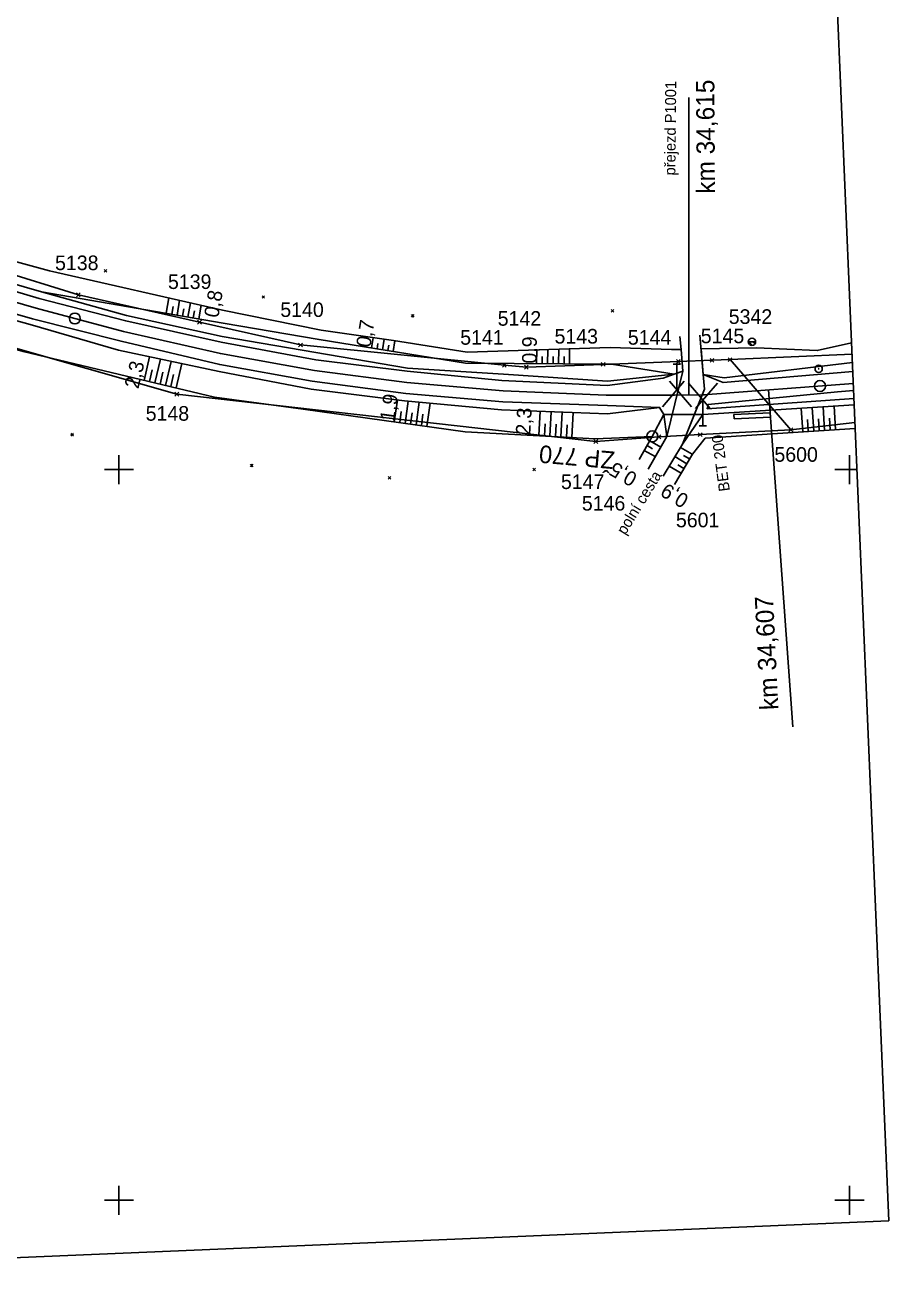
# Model space of a CAD drawing. Extents: x -806456 to -805395, y -1150847 to -1150506.
# Drawn here: x -805512.8 to -805394.6, y -1150811.7 to -1150639.2 of the extents above; entities that cross this region are included whole.
import ezdxf

# ---------------------------------------------------------------- set-up
doc = ezdxf.new("R2010")
doc.units = 0
for name, color, linetype in [('0381KM032-037P - Vrstva 1', 7, 'Continuous'), ('0381KM032-037P - Vrstva 19', 7, 'Continuous'), ('0381KM032-037P - Vrstva 36', 7, 'Continuous'), ('0381KM032-037P - Vrstva 4', 7, 'Continuous'), ('0381KM032-037P - Vrstva 48', 7, 'Continuous'), ('0381KM032-037P - Vrstva 49', 7, 'Continuous'), ('0381KM032-037P - Vrstva 51', 7, 'Continuous'), ('0381KM032-037P - Vrstva 55', 7, 'Continuous'), ('0381KM032-037P - Vrstva 7', 7, 'Continuous'), ('0381KM032-037P - Vrstva 9', 7, 'Continuous'), ('formát', 7, 'Continuous'), ('krizky_1000 - Vrstva 1', 7, 'Continuous'), ('szdc - hran DP', 7, 'Continuous'), ('szdc - szdc_cislo', 7, 'Continuous'), ('szdc - szdc_krizek', 7, 'Continuous'), ('vyt_sit - stávající', 7, 'Continuous')]:
    doc.layers.add(name, color=color, linetype=linetype)

msp = doc.modelspace()

# ---------------------------------------------------------------- linework, layer by layer
at = {"layer": '0381KM032-037P - Vrstva 1'}
for points in [[(-805499.4, -1150681.08), (-805511.35, -1150677.89), (-805524.48, -1150674.12), (-805529.81, -1150672.54)], [(-805399.47, -1150688.2), (-805419.96, -1150689.78), (-805423.96, -1150689.8), (-805433.29, -1150689.8), (-805447.38, -1150689.21), (-805460.61, -1150688.07), (-805473.24, -1150686.41), (-805486.12, -1150684.11), (-805499.4, -1150681.08)]]:
    msp.add_lwpolyline(points, dxfattribs=at)
at = {"layer": '0381KM032-037P - Vrstva 19'}
msp.add_line((-805425.41, -1150692.47), (-805420.07, -1150692.47), dxfattribs=at)
at = {"layer": '0381KM032-037P - Vrstva 36'}
for p, q in [((-805413.84, -1150682.5), (-805412.84, -1150682.5)), ((-805412.84, -1150682.5), (-805413.84, -1150682.5)), ((-805413.28, -1150683), (-805413.77, -1150682.5)), ((-805412.94, -1150682.8), (-805413.24, -1150682.5))]:
    msp.add_line(p, q, dxfattribs=at)
msp.add_circle((-805413.34, -1150682.5), 0.503, dxfattribs=at)
msp.add_arc((-805413.34, -1150682.5), 0.503, 180, 0, dxfattribs=at)
at = {"layer": '0381KM032-037P - Vrstva 4'}
for p, q in [((-805421.99, -1150689.77), (-805421.99, -1150649.07)), ((-805423.11, -1150685.55), (-805424.11, -1150685.55)), ((-805423.61, -1150685.55), (-805423.61, -1150689.05)), ((-805422.61, -1150687.9), (-805425.61, -1150691.4)), ((-805421.61, -1150691.4), (-805424.61, -1150687.9)), ((-805422.05, -1150688.15), (-805419.05, -1150691.65)), ((-805421.05, -1150691.65), (-805418.05, -1150688.15)), ((-805423.96, -1150689.8), (-805419.82, -1150689.74)), ((-805420.05, -1150694), (-805420.05, -1150690.5)), ((-805420.55, -1150694), (-805419.55, -1150694))]:
    msp.add_line(p, q, dxfattribs=at)
for points in [[(-805485.85, -1150681.76), (-805498.96, -1150678.92), (-805510.6, -1150675.66), (-805525.22, -1150671.48), (-805544.53, -1150665.72), (-805562.31, -1150661.11), (-805574.56, -1150658.15), (-805590.74, -1150655.42), (-805602.22, -1150654.14), (-805617.62, -1150652.74), (-805630.08, -1150651.83), (-805647.65, -1150650.8), (-805688.26, -1150650.5)], [(-805423.97, -1150686.92), (-805425.51, -1150687.49), (-805433.17, -1150688.49), (-805447.58, -1150687.79), (-805460.54, -1150686.52), (-805473.03, -1150684.97), (-805486, -1150682.53), (-805499.06, -1150679.64), (-805510.93, -1150676.58), (-805525.41, -1150672.29), (-805545.14, -1150666.47), (-805562.36, -1150661.85), (-805574.71, -1150659.28), (-805590.7, -1150656.46), (-805602.42, -1150654.96), (-805617.57, -1150653.8), (-805630.08, -1150653.28), (-805647.6, -1150652.35), (-805687.98, -1150651.47)], [(-805425.98, -1150691.47), (-805433.13, -1150691.22), (-805447.47, -1150690.71), (-805460.74, -1150689.57), (-805473.54, -1150687.87), (-805486.2, -1150685.62), (-805499.7, -1150682.42), (-805511.82, -1150679.35), (-805526.11, -1150675.23), (-805545.84, -1150669.48), (-805563.16, -1150664.96), (-805575.57, -1150662.2), (-805590.62, -1150659.46), (-805602.86, -1150658.06), (-805617.64, -1150656.78), (-805630.16, -1150656.16), (-805647.73, -1150655.65), (-805688.15, -1150654.42)], [(-805425.41, -1150692.47), (-805425.98, -1150691.47), (-805433.11, -1150692.35), (-805447.61, -1150691.82), (-805460.9, -1150690.59), (-805473.67, -1150688.98), (-805486.26, -1150686.57), (-805500.08, -1150683.65), (-805512.15, -1150680.12), (-805526.27, -1150676.26), (-805545.98, -1150670.57), (-805563.42, -1150665.87), (-805575.79, -1150663.12), (-805590.93, -1150660.59), (-805603.28, -1150659.09), (-805617.92, -1150657.97), (-805630.11, -1150657.32), (-805646.66, -1150657.1), (-805648.58, -1150657.2), (-805687.42, -1150655.93)], [(-805423.97, -1150686.92), (-805433.1, -1150687.91), (-805447.34, -1150686.91), (-805460.49, -1150686.09), (-805485.85, -1150681.76)], [(-805399.6, -1150685.34), (-805417.14, -1150687.42), (-805420, -1150686.97)], [(-805399.54, -1150686.56), (-805417.27, -1150688.09), (-805420, -1150686.97)], [(-805399.43, -1150689.16), (-805401.63, -1150689.36), (-805419.33, -1150691.07), (-805419.49, -1150691.68)], [(-805399.39, -1150690.24), (-805419.49, -1150691.68)]]:
    msp.add_lwpolyline(points, dxfattribs=at)
at = {"layer": '0381KM032-037P - Vrstva 48'}
for p, q in [((-805493.52, -1150678.6), (-805493.15, -1150676.49)), ((-805492.78, -1150678.73), (-805492.6, -1150677.69)), ((-805492.04, -1150678.85), (-805491.69, -1150676.82)), ((-805491.3, -1150678.98), (-805491.13, -1150677.99)), ((-805490.56, -1150679.11), (-805490.22, -1150677.16)), ((-805489.82, -1150679.23), (-805489.66, -1150678.28)), ((-805489.08, -1150679.36), (-805488.76, -1150677.49)), ((-805465.41, -1150683.34), (-805465.19, -1150681.94)), ((-805464.67, -1150683.46), (-805464.56, -1150682.75)), ((-805463.93, -1150683.58), (-805463.7, -1150682.16)), ((-805463.19, -1150683.7), (-805463.07, -1150682.98)), ((-805462.45, -1150683.82), (-805462.22, -1150682.37)), ((-805441.32, -1150685.5), (-805441.3, -1150683.55)), ((-805439.82, -1150685.51), (-805439.8, -1150683.51)), ((-805438.32, -1150685.52), (-805438.3, -1150683.46)), ((-805496.56, -1150687.78), (-805495.8, -1150684.56)), ((-805495.1, -1150688.12), (-805494.33, -1150684.87)), ((-805493.64, -1150688.47), (-805492.86, -1150685.18)), ((-805442.82, -1150685.49), (-805442.8, -1150683.6)), ((-805442.07, -1150685.49), (-805442.06, -1150684.53)), ((-805440.57, -1150685.5), (-805440.56, -1150684.52)), ((-805439.07, -1150685.51), (-805439.06, -1150684.5)), ((-805495.83, -1150687.95), (-805495.45, -1150686.33)), ((-805494.37, -1150688.3), (-805493.98, -1150686.66)), ((-805492.91, -1150688.64), (-805492.52, -1150686.99)), ((-805492.18, -1150688.82), (-805491.39, -1150685.49)), ((-805462.31, -1150693.46), (-805461.89, -1150690.47)), ((-805461.56, -1150693.56), (-805461.35, -1150692.06)), ((-805460.82, -1150693.66), (-805460.4, -1150690.64)), ((-805459.33, -1150693.87), (-805458.91, -1150690.78)), ((-805457.85, -1150694.07), (-805457.41, -1150690.91)), ((-805442.5, -1150695.34), (-805442.32, -1150692.01)), ((-805441, -1150695.43), (-805440.82, -1150692.07)), ((-805439.5, -1150695.51), (-805439.32, -1150692.12)), ((-805438, -1150695.59), (-805437.82, -1150692.18)), ((-805406.38, -1150694.81), (-805406.59, -1150691.59)), ((-805404.88, -1150694.71), (-805405.09, -1150691.49)), ((-805403.39, -1150694.62), (-805403.59, -1150691.39)), ((-805401.89, -1150694.52), (-805402.09, -1150691.3)), ((-805460.08, -1150693.77), (-805459.86, -1150692.24)), ((-805458.59, -1150693.97), (-805458.38, -1150692.41)), ((-805441.75, -1150695.39), (-805441.66, -1150693.71)), ((-805440.25, -1150695.47), (-805440.16, -1150693.78)), ((-805438.75, -1150695.55), (-805438.66, -1150693.85)), ((-805405.63, -1150694.76), (-805405.73, -1150693.15)), ((-805404.13, -1150694.66), (-805404.24, -1150693.05)), ((-805402.64, -1150694.57), (-805402.74, -1150692.96)), ((-805428.08, -1150697.36), (-805426.58, -1150698.22)), ((-805427.71, -1150696.71), (-805426.96, -1150697.14)), ((-805427.34, -1150696.06), (-805425.83, -1150696.92)), ((-805421.51, -1150697.9), (-805423.11, -1150696.95)), ((-805422.27, -1150699.19), (-805423.9, -1150698.22)), ((-805421.89, -1150698.54), (-805422.7, -1150698.06)), ((-805423.04, -1150700.48), (-805424.68, -1150699.5)), ((-805422.66, -1150699.83), (-805423.47, -1150699.35))]:
    msp.add_line(p, q, dxfattribs=at)
at = {"layer": '0381KM032-037P - Vrstva 49'}
for p, q in [((-805501.66, -1150672.97), (-805502.01, -1150672.62)), ((-805501.66, -1150672.62), (-805502.01, -1150672.97)), ((-805480.06, -1150676.54), (-805480.41, -1150676.19)), ((-805480.06, -1150676.19), (-805480.41, -1150676.54)), ((-805432.26, -1150678.45), (-805432.61, -1150678.1)), ((-805432.26, -1150678.1), (-805432.61, -1150678.45)), ((-805459.62, -1150679.12), (-805459.97, -1150678.77)), ((-805459.62, -1150678.77), (-805459.97, -1150679.12)), ((-805426.99, -1150695.45), (-805425.41, -1150692.47)), ((-805506.23, -1150695.39), (-805506.58, -1150695.03)), ((-805506.23, -1150695.03), (-805506.58, -1150695.39)), ((-805481.65, -1150699.61), (-805482, -1150699.26)), ((-805481.65, -1150699.26), (-805482, -1150699.61)), ((-805442.98, -1150700.16), (-805443.33, -1150699.81)), ((-805442.98, -1150699.81), (-805443.33, -1150700.16)), ((-805462.79, -1150701.28), (-805463.14, -1150700.93)), ((-805462.79, -1150700.93), (-805463.14, -1150701.28))]:
    msp.add_line(p, q, dxfattribs=at)
for points in [[(-805423.97, -1150686.92), (-805433.1, -1150687.91), (-805447.34, -1150686.91), (-805460.49, -1150686.09), (-805485.85, -1150681.76), (-805498.96, -1150678.92), (-805510.6, -1150675.66), (-805525.22, -1150671.48), (-805544.53, -1150665.72), (-805562.31, -1150661.11), (-805571.99, -1150658.79), (-805574.56, -1150658.15), (-805590.74, -1150655.42), (-805602.22, -1150654.14), (-805617.62, -1150652.74), (-805630.08, -1150651.83), (-805647.65, -1150650.8), (-805688.26, -1150650.5)], [(-805424.36, -1150683.57), (-805432.74, -1150683.28), (-805452.35, -1150683.91), (-805462.43, -1150682.34), (-805472.3, -1150680.9), (-805485.84, -1150678.15), (-805509.51, -1150672.79), (-805524.62, -1150668.67), (-805544.15, -1150662.92), (-805562.19, -1150658.51), (-805574.34, -1150655.56), (-805587.56, -1150653.68), (-805602.19, -1150651.94)], [(-805425.41, -1150692.47), (-805425.98, -1150691.47), (-805433.11, -1150692.35), (-805447.61, -1150691.82), (-805460.9, -1150690.59), (-805473.67, -1150688.98), (-805486.26, -1150686.57), (-805500.08, -1150683.65), (-805512.15, -1150680.12), (-805526.27, -1150676.26), (-805545.98, -1150670.57), (-805563.42, -1150665.87), (-805575.79, -1150663.12), (-805590.93, -1150660.59), (-805603.28, -1150659.09), (-805617.92, -1150657.97), (-805630.11, -1150657.32), (-805646.15, -1150657.11), (-805646.27, -1150657.1), (-805646.57, -1150657.13), (-805646.66, -1150657.1), (-805648.58, -1150657.2), (-805687.42, -1150655.93)], [(-805428.8, -1150698.61), (-805426.99, -1150695.45), (-805434.79, -1150695.76), (-805452.59, -1150694.8), (-805474.79, -1150691.73), (-805486.9, -1150690.07), (-805513.13, -1150683.83), (-805526.69, -1150679.91), (-805538.18, -1150675.92), (-805547.05, -1150672.92), (-805563.97, -1150668.42), (-805576.87, -1150665.35), (-805586.81, -1150663.24), (-805590.73, -1150662.74), (-805601.92, -1150661.35), (-805629.88, -1150659.22), (-805648.74, -1150658.99), (-805687.58, -1150660.02)], [(-805422.8, -1150686.53), (-805423.97, -1150686.92), (-805432.55, -1150685.56), (-805452.56, -1150685.41), (-805472.6, -1150682.19), (-805485.72, -1150679.94), (-805510.6, -1150675.66)], [(-805422.8, -1150686.53), (-805423.05, -1150683.54), (-805424.36, -1150683.57)], [(-805412.74, -1150683.31), (-805420.31, -1150683.48), (-805420, -1150686.97)], [(-805412.74, -1150683.31), (-805404.41, -1150683.71), (-805399.71, -1150682.62)], [(-805420, -1150686.97), (-805417.14, -1150687.42), (-805399.6, -1150685.34)], [(-805420.07, -1150692.47), (-805399.35, -1150691.12)], [(-805427.56, -1150699.92), (-805424.99, -1150695.46), (-805425.41, -1150692.47)], [(-805420.07, -1150692.47), (-805422.84, -1150696.5), (-805425.52, -1150700.88)], [(-805419.74, -1150695.67), (-805399.21, -1150694.35)], [(-805423.96, -1150702.03), (-805421.5, -1150697.89), (-805419.74, -1150695.67)]]:
    msp.add_lwpolyline(points, dxfattribs=at)
at = {"layer": '0381KM032-037P - Vrstva 51'}
for points in [[(-805425.52, -1150700.88), (-805422.84, -1150696.5), (-805419.83, -1150688.97), (-805420, -1150686.97), (-805420.48, -1150681.6)], [(-805422.8, -1150686.53), (-805423.05, -1150683.54), (-805423.2, -1150681.79)], [(-805422.8, -1150686.53), (-805424.99, -1150695.46), (-805427.56, -1150699.92)]]:
    msp.add_lwpolyline(points, dxfattribs=at)
at = {"layer": '0381KM032-037P - Vrstva 55'}
msp.add_line((-805416.34, -1150684.94), (-805408.01, -1150694.56), dxfattribs=at)
at = {"layer": '0381KM032-037P - Vrstva 7'}
msp.add_line((-805404.26, -1150686.19), (-805404.16, -1150686.19), dxfattribs=at)
for centre, radius in [((-805506.04, -1150679.31), 0.75), ((-805404.21, -1150686.19), 0.5), ((-805404.03, -1150688.55), 0.75)]:
    msp.add_circle(centre, radius, dxfattribs=at)
at = {"layer": '0381KM032-037P - Vrstva 9'}
for p, q in [((-805411.08, -1150689.08), (-805407.73, -1150735.22)), ((-805410.84, -1150692.23), (-805410.86, -1150691.64)), ((-805410.84, -1150692.23), (-805415.83, -1150692.47)), ((-805415.83, -1150692.47), (-805415.8, -1150693.06)), ((-805415.8, -1150693.06), (-805410.81, -1150692.82)), ((-805410.81, -1150692.82), (-805410.84, -1150692.23))]:
    msp.add_line(p, q, dxfattribs=at)
at = {"layer": 'formát'}
for p, q in [((-805407.21, -1150506.06), (-805394.61, -1150802.8)), ((-805394.61, -1150802.8), (-805604.42, -1150811.7))]:
    msp.add_line(p, q, dxfattribs=at)
at = {"layer": 'krizky_1000 - Vrstva 1'}
for points in [[(-805500, -1150698), (-805500, -1150702)], [(-805400, -1150698), (-805400, -1150702)], [(-805502, -1150700), (-805498, -1150700)], [(-805402, -1150700), (-805398.97, -1150700)], [(-805500, -1150798), (-805500, -1150802)], [(-805400, -1150798), (-805400, -1150802)], [(-805502, -1150800), (-805498, -1150800)], [(-805402, -1150800), (-805398, -1150800)]]:
    msp.add_lwpolyline(points, dxfattribs=at)
at = {"layer": 'szdc - hran DP'}
for p, q in [((-805522.57, -1150670.78), (-805505.56, -1150676.07)), ((-805505.56, -1150676.07), (-805488.96, -1150679.81)), ((-805492.06, -1150689.65), (-805525.6, -1150680.1)), ((-805488.96, -1150679.81), (-805475.13, -1150682.93)), ((-805475.13, -1150682.93), (-805447.24, -1150685.68)), ((-805433.7, -1150685.59), (-805423.42, -1150685.2)), ((-805423.42, -1150685.2), (-805418.81, -1150685.03)), ((-805418.81, -1150685.03), (-805416.34, -1150684.94)), ((-805416.34, -1150684.94), (-805399.64, -1150684.18)), ((-805447.24, -1150685.68), (-805444.22, -1150685.98)), ((-805444.22, -1150685.98), (-805433.7, -1150685.59)), ((-805434.71, -1150696.14), (-805492.06, -1150689.65)), ((-805399.25, -1150693.56), (-805408.01, -1150694.56)), ((-805426.08, -1150695.49), (-805434.71, -1150696.14)), ((-805420.42, -1150695.2), (-805426.08, -1150695.49)), ((-805408.01, -1150694.56), (-805420.42, -1150695.2))]:
    msp.add_line(p, q, dxfattribs=at)
at = {"layer": 'szdc - szdc_krizek'}
for p, q in [((-805505.3, -1150676.33), (-805505.83, -1150675.8)), ((-805505.83, -1150676.33), (-805505.3, -1150675.8)), ((-805488.7, -1150680.07), (-805489.23, -1150679.54)), ((-805489.23, -1150680.07), (-805488.7, -1150679.54)), ((-805474.86, -1150683.2), (-805475.4, -1150682.67)), ((-805475.4, -1150683.2), (-805474.86, -1150682.67)), ((-805423.16, -1150685.47), (-805423.69, -1150684.94)), ((-805423.69, -1150685.47), (-805423.16, -1150684.94)), ((-805418.55, -1150685.29), (-805419.08, -1150684.77)), ((-805419.08, -1150685.29), (-805418.55, -1150684.77)), ((-805416.08, -1150685.21), (-805416.61, -1150684.68)), ((-805416.61, -1150685.21), (-805416.08, -1150684.68)), ((-805446.97, -1150685.95), (-805447.51, -1150685.42)), ((-805447.51, -1150685.95), (-805446.97, -1150685.42)), ((-805443.96, -1150686.25), (-805444.49, -1150685.72)), ((-805444.49, -1150686.25), (-805443.96, -1150685.72)), ((-805433.44, -1150685.85), (-805433.97, -1150685.32)), ((-805433.97, -1150685.85), (-805433.44, -1150685.32)), ((-805491.8, -1150689.92), (-805492.33, -1150689.39)), ((-805492.33, -1150689.92), (-805491.8, -1150689.39)), ((-805425.82, -1150695.76), (-805426.35, -1150695.23)), ((-805426.35, -1150695.76), (-805425.82, -1150695.23)), ((-805420.16, -1150695.47), (-805420.69, -1150694.94)), ((-805420.69, -1150695.47), (-805420.16, -1150694.94)), ((-805407.74, -1150694.82), (-805408.28, -1150694.29)), ((-805408.28, -1150694.82), (-805407.74, -1150694.29)), ((-805434.45, -1150696.41), (-805434.98, -1150695.88)), ((-805434.98, -1150696.41), (-805434.45, -1150695.88))]:
    msp.add_line(p, q, dxfattribs=at)
at = {"layer": 'vyt_sit - stávající'}
msp.add_line((-805427.04, -1150695.45), (-805426.94, -1150695.45), dxfattribs=at)
msp.add_circle((-805426.99, -1150695.45), 0.756, dxfattribs=at)

# ---------------------------------------------------------------- texts
at = {"layer": '0381KM032-037P - Vrstva 19'}
msp.add_text('BET 200', height=1.5, rotation=97.5063, dxfattribs=at).set_placement((-805416.36, -1150702.88))
at = {"layer": '0381KM032-037P - Vrstva 4'}
for s, height, rotation, p in [('přejezd P1001', 1.5, 89.4547, (-805423.83, -1150659.74)), ('km 34,615', 2.5, 90.3142, (-805418.41, -1150662.22))]:
    msp.add_text(s, height=height, rotation=rotation, dxfattribs=at).set_placement(p)
at = {"layer": '0381KM032-037P - Vrstva 48'}
for s, rotation, p in [('0,8', 80.2414, (-805486.4, -1150679.29)), ('0,7', 80.8528, (-805465.58, -1150683.35)), ('0,9', 89.5678, (-805442.82, -1150685.49)), ('2,3', 76.6332, (-805497.34, -1150689.02)), ('1,9', 82.1252, (-805462.31, -1150693.46)), ('2,3', 86.8943, (-805443.69, -1150695.28)), ('0,5', 150.2278, (-805428.88, -1150700.69)), ('0,9', 149.2587, (-805421.83, -1150703.66))]:
    msp.add_text(s, height=2, rotation=rotation, dxfattribs=at).set_placement(p)
at = {"layer": '0381KM032-037P - Vrstva 51'}
msp.add_text('polní cesta', height=1.5, rotation=58.5387, dxfattribs=at).set_placement((-805430.69, -1150709.03))
at = {"layer": '0381KM032-037P - Vrstva 9'}
msp.add_text('km 34,607', height=2.5, rotation=92.7706, dxfattribs=at).set_placement((-805409.71, -1150732.84))
at = {"layer": 'szdc - szdc_cislo'}
for s, p in [('5138', (-805508.75, -1150672.69)), ('5139', (-805493.29, -1150675.27)), ('5140', (-805477.91, -1150679.1)), ('5142', (-805448.15, -1150680.3)), ('5342', (-805416.52, -1150680.05)), ('5141', (-805453.28, -1150682.9)), ('5143', (-805440.37, -1150682.74)), ('5144', (-805430.33, -1150682.89)), ('5145', (-805420.35, -1150682.69)), ('5148', (-805496.34, -1150693.3)), ('5600', (-805410.27, -1150698.92)), ('5147', (-805439.49, -1150702.65)), ('5146', (-805436.63, -1150705.6)), ('5601', (-805423.75, -1150707.89))]:
    msp.add_text(s, height=2, dxfattribs=at).set_placement(p)
at = {"layer": 'vyt_sit - stávající'}
msp.add_text('ŽP 770', height=2.4, rotation=175, dxfattribs=at).set_placement((-805432.05, -1150697.54))

doc.saveas('drawing.dxf')
